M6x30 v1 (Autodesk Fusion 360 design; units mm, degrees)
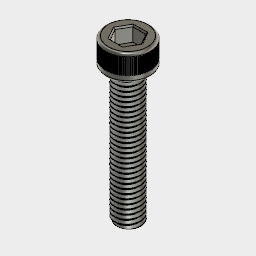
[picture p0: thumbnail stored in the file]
sketch "スケッチ1"
  circle C1 centre (0, 0) radius 3
  circle C2 centre (0, 0) radius 5
  dimension "d1" diameter C1 = 6
  dimension "d2" diameter C2 = 10
extrude "押し出し1" new body sketch "スケッチ1" blind 5.8
sketch "スケッチ2" plane through (0, 0, 5.8) normal (0, 0, 1) x axis (-1, 0, 0)
  line L1 (-1.4722, -2.55) -> (-2.9445, 0)
  line L2 (1.4722, -2.55) -> (-1.4722, -2.55)
  line L3 (2.9445, 0) -> (1.4722, -2.55)
  line L4 (1.4722, 2.55) -> (2.9445, 0)
  line L5 (-1.4722, 2.55) -> (1.4722, 2.55)
  line L6 (-2.9445, 0) -> (-1.4722, 2.55)
  circle C1 centre (0, 0) radius 5
  dimension "d5" distance L2 L5 = 5.1
work_plane "作業平面" sketch "スケッチ2" AlongDistance -0.75
extrude "押し出し2" cut sketch "スケッチ2" profile of L1 L2 L3 L4 L5 L6 against normal blind 3.3
chamfer "面取り" distance 0.3
sketch "スケッチ3" plane through (0, 0, 5.05) normal (0, 0, 1) x axis (1, 0, 0)
  line L1 (-0.05, 4.9497) -> (-0.05, 4.9997)
  line L2 (0.05, 4.9497) -> (-0.05, 4.9497)
  line L3 (0.05, 4.9997) -> (0.05, 4.9497)
  circle C1 centre (0, 0) radius 5
  point P4 (-0.05, 4.9497)
  point P5 (0.05, 4.9497)
  point P3 (-0.05, 4.9997)
  point P6 (0.05, 4.9997)
  dimension "d18" distance P4 P5 = 0.1
  dimension "d19" distance P3 P4 = 0.05
  dimension "d20" distance P5 P6 = 0.05 (= "d19")
extrude "押し出し3" cut sketch "スケッチ3" against normal blind 3.6
work_axis "作業軸"
circular_pattern "C パターン" countU 100 TotalAngle 360
fillet "フィレット1" radius 0.6
extrude "押し出し4" add sketch "スケッチ1" profile of C1 blind -30
thread "ねじ"
fillet "フィレット2" sketch "スケッチ3" radius 0.5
